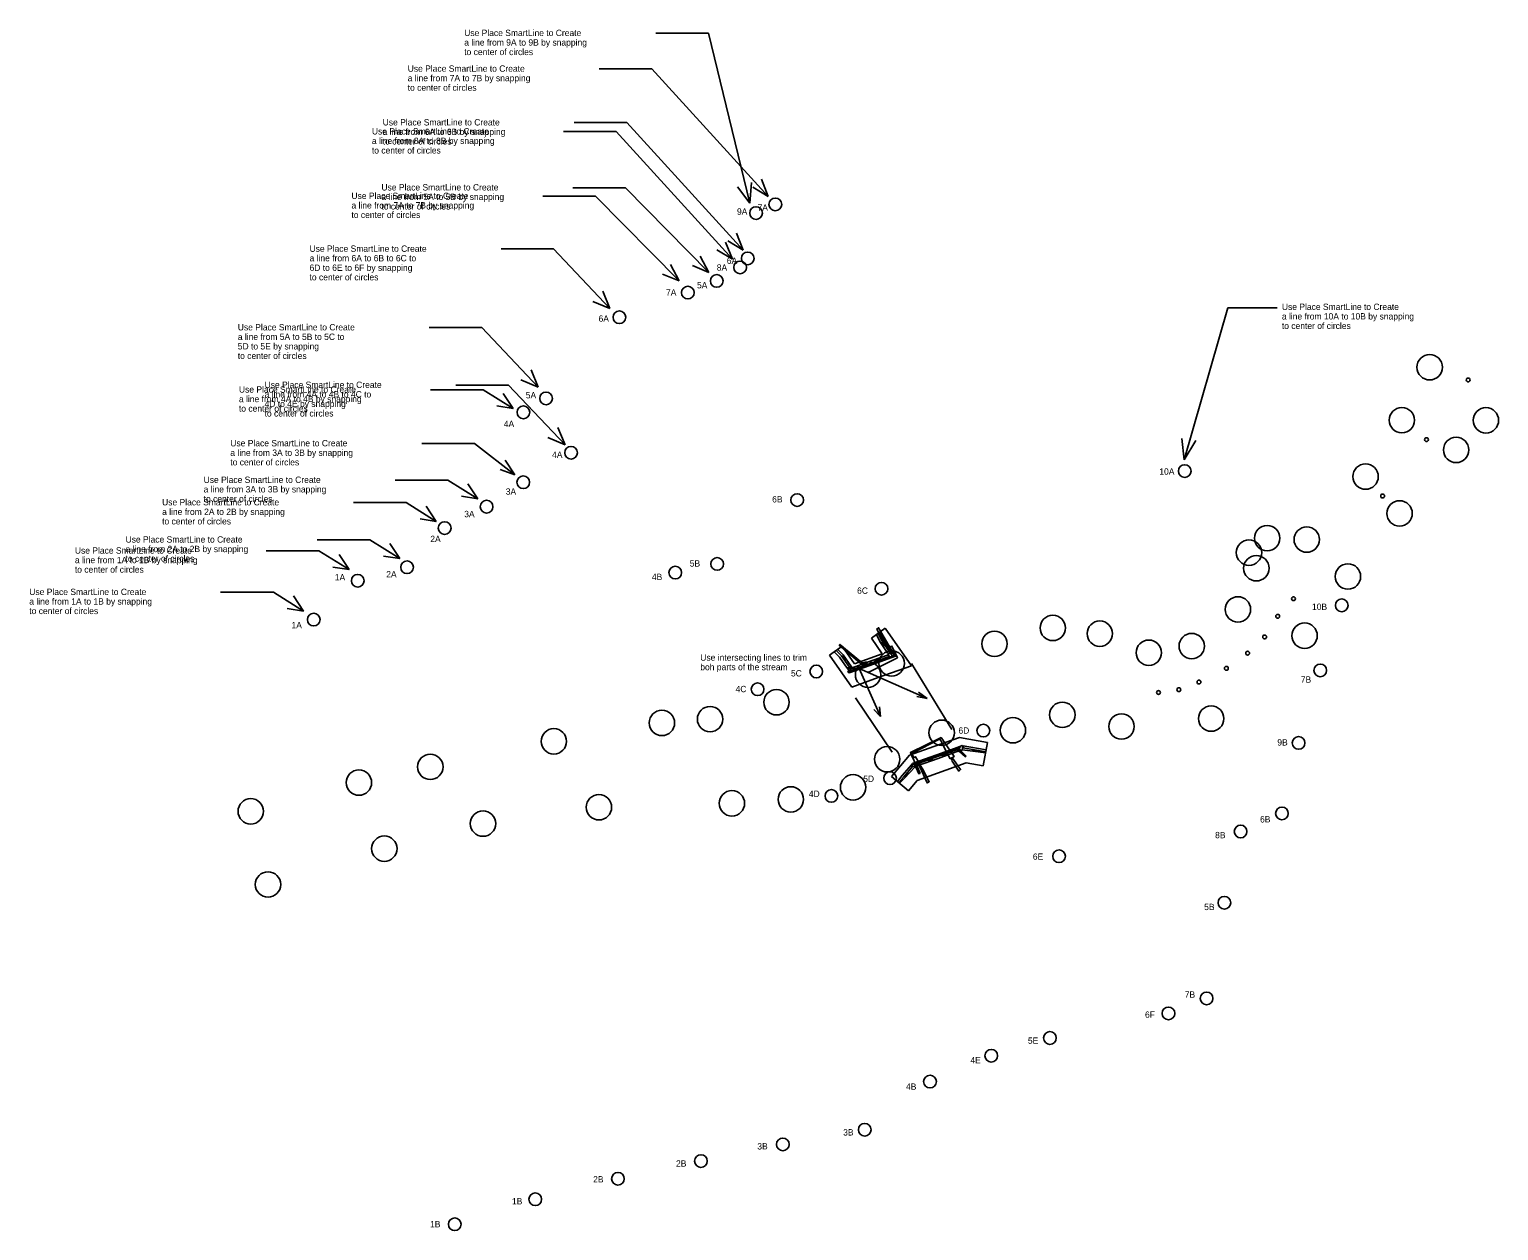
# Model space of a CAD drawing. Extents: x 74477 to 81269, y 49330 to 50934.
# Drawn here: x 74477 to 75634, y 49330 to 50276 of the extents above; entities that cross this region are included whole.
import ezdxf

# ---------------------------------------------------------------- set-up
doc = ezdxf.new("R2010")
doc.units = 0
for name, color, linetype in [('1', 7, 'Continuous'), ('13', 7, 'Continuous'), ('2', 7, 'Continuous'), ('3', 7, 'Continuous'), ('4', 7, 'Continuous'), ('5', 7, 'Continuous'), ('6', 7, 'Continuous')]:
    doc.layers.add(name, color=color, linetype=linetype)

msp = doc.modelspace()

# ---------------------------------------------------------------- linework, layer by layer
at = {"layer": '1'}
for points in [[(75156.2, 49784.7), (75157.2, 49785.3), (75155.7, 49787.9), (75155.5, 49787.9), (75145.7, 49804.9), (75144.2, 49803.9), (75149.4, 49794.7), (75153.4, 49787.8), (75154.9, 49786.9)], [(75134.7, 49773.5), (75133.2, 49775), (75131, 49777.3), (75114.7, 49791.2), (75115.2, 49791.8), (75131.5, 49778.5), (75134, 49776.2), (75135.4, 49774.1)], [(75154.6, 49789.8), (75156.2, 49790.5), (75160.6, 49781.3), (75137.4, 49769.7), (75137, 49770.4)], [(75194, 49717.1), (75195.4, 49714.8), (75195.4, 49714.3), (75202.2, 49701.8), (75205.2, 49703.5), (75197, 49715.4), (75196.8, 49715.8), (75194.9, 49718.5), (75170.8, 49706.6), (75172.5, 49702.9), (75172.6, 49702.4), (75174.6, 49698.2), (75177.1, 49699.3), (75174.8, 49703.4), (75173.5, 49702.8), (75173.2, 49703.1), (75171.8, 49705.9), (75193.6, 49717.2)], [(75176.7, 49698.8), (75183.9, 49682.8), (75185.6, 49683.7), (75180.3, 49693.8), (75177.2, 49698.8)], [(75177.2, 49698.8), (75176.7, 49698.8)], [(75203.1, 49701.9), (75203.6, 49700), (75209, 49692), (75210.3, 49693.2), (75204.8, 49701.2), (75203.9, 49702.2)], [(75203.9, 49702.2), (75203.1, 49701.9)]]:
    msp.add_lwpolyline(points, dxfattribs=at)
at = {"layer": '13'}
for centre in [(75579.7, 50010.1), (75557.8, 49968.4), (75624, 49968.3), (75600.5, 49945), (75529.2, 49924), (75556, 49895), (75451.7, 49875.5), (75482.9, 49874.4), (75437.4, 49864.1), (75443.2, 49851.8), (75515.3, 49845.3), (75428.7, 49819.4), (75282.9, 49804.8), (75319.9, 49800.3), (75481.2, 49798.7), (75237, 49792.3), (75392.3, 49790.5), (75156, 49776.9), (75358.5, 49785.3), (75137.4, 49768), (75065.3, 49746.3), (74975.1, 49730), (75013, 49733), (75290.4, 49736.4), (75407.6, 49733.4), (75195.4, 49722.3), (75251.5, 49724.2), (75337, 49727.2), (74890, 49715.5), (74792.7, 49695.4), (75152.5, 49701.4), (74736.5, 49683), (75125.6, 49679.3), (74651.3, 49660.4), (74925.5, 49663.6), (75030.2, 49666.7), (75076.6, 49669.8), (74834.2, 49650.7), (74756.5, 49631), (74664.9, 49602.8)]:
    msp.add_circle(centre, 10, dxfattribs=at)
at = {"layer": '2'}
for p, q in [((75151, 49804.5), (75140, 49796.8)), ((75144.1, 49799.7), (75146.9, 49801.6)), ((75146.6, 49794.2), (75144.1, 49799.7)), ((75145.5, 49800.6), (75148, 49795.2)), ((75146.9, 49801.6), (75149.4, 49796.2)), ((75171.5, 49775), (75151, 49804.5)), ((75107.1, 49783.4), (75117.1, 49790.4)), ((75115, 49781.8), (75110.8, 49786)), ((75116.5, 49782.8), (75112.2, 49787)), ((75113.5, 49787.9), (75117.7, 49783.7)), ((75117.1, 49790.4), (75126.8, 49776.5)), ((75140, 49796.8), (75148.6, 49784.3)), ((75153.1, 49784.7), (75146.6, 49794.2)), ((75149, 49793.7), (75147.6, 49792.7)), ((75148, 49795.2), (75154.8, 49785.3)), ((75149.5, 49792.9), (75148.1, 49791.9)), ((75149.3, 49793.3), (75148.6, 49792.8)), ((75150.1, 49792.1), (75148.7, 49791.1)), ((75149.8, 49792.5), (75149.1, 49792)), ((75150.7, 49791.3), (75149.2, 49790.3)), ((75149.4, 49796.2), (75156.5, 49785.9)), ((75150.4, 49791.7), (75149.7, 49791.2)), ((75156.5, 49785.9), (75153.1, 49784.7)), ((75107.1, 49783.4), (75124.6, 49758.2)), ((75121, 49773.1), (75115, 49781.8)), ((75122.7, 49773.8), (75116.5, 49782.8)), ((75118.2, 49783), (75116.9, 49782.1)), ((75117.2, 49781.7), (75117.8, 49782.2)), ((75118.8, 49782.2), (75117.5, 49781.3)), ((75117.7, 49783.7), (75124.4, 49774.3)), ((75117.7, 49780.9), (75118.4, 49781.3)), ((75119.3, 49781.4), (75118, 49780.5)), ((75118.3, 49780.1), (75118.9, 49780.5)), ((75119.9, 49780.6), (75118.6, 49779.7)), ((75124.4, 49774.3), (75121, 49773.1)), ((75121.8, 49769.9), (75141.4, 49777)), ((75123.4, 49769.7), (75141.6, 49776.2)), ((75140.6, 49779.1), (75124.9, 49773.5)), ((75125.8, 49772.2), (75141.1, 49777.7)), ((75148.6, 49784.3), (75126.8, 49776.5)), ((75133.8, 49775), (75133.3, 49776.5)), ((75134.3, 49775.2), (75134, 49775.9)), ((75134.8, 49775.4), (75134.2, 49776.8)), ((75135.2, 49775.5), (75135, 49776.3)), ((75135.7, 49775.7), (75135.2, 49777.2)), ((75136.2, 49775.9), (75135.9, 49776.6)), ((75136.6, 49776.1), (75136.1, 49777.5)), ((75138.6, 49775.2), (75138.2, 49775)), ((75140.6, 49779.1), (75153.4, 49783.7)), ((75154, 49782.3), (75141.1, 49777.7)), ((75141.4, 49777), (75159.6, 49783.5)), ((75141.6, 49776.2), (75158.9, 49782.5)), ((75143.2, 49778.4), (75142.7, 49779.9)), ((75143.7, 49778.6), (75143.4, 49779.3)), ((75144.1, 49778.7), (75143.6, 49780.2)), ((75144.6, 49778.9), (75144.3, 49779.6)), ((75145.1, 49779.1), (75144.5, 49780.6)), ((75145.5, 49779.2), (75145.3, 49780)), ((75145.4, 49765.7), (75171.5, 49775)), ((75146, 49779.4), (75145.5, 49780.9)), ((75153.4, 49783.7), (75154, 49782.3)), ((75124.6, 49758.2), (75145.4, 49765.7)), ((75124.9, 49773.5), (75125.8, 49772.2)), ((75209.3, 49718.6), (75189.2, 49711.4)), ((75231.4, 49714.6), (75209.3, 49718.6)), ((75170.1, 49704.6), (75156, 49687.9)), ((75189.2, 49711.4), (75170.1, 49704.6)), ((75191.6, 49704.9), (75172.9, 49698.2)), ((75208.5, 49711), (75191.6, 49704.9)), ((75210.1, 49710.8), (75191.8, 49704.2)), ((75208, 49709.2), (75192.1, 49703.5)), ((75192.6, 49702.1), (75208.8, 49708)), ((75194.6, 49706), (75195, 49706.2)), ((75195.8, 49704.8), (75196.3, 49703.5)), ((75196.2, 49705), (75196.5, 49704.3)), ((75196.7, 49705.2), (75197.2, 49703.8)), ((75197.2, 49705.3), (75197.4, 49704.7)), ((75197.7, 49705.5), (75198.2, 49704.1)), ((75198.1, 49705.7), (75198.4, 49705)), ((75198.6, 49705.9), (75199.1, 49704.5)), ((75209.4, 49709.7), (75208, 49709.2)), ((75209.3, 49707.3), (75208, 49709.2)), ((75208, 49709.2), (75209.3, 49707.3)), ((75208.8, 49708), (75208, 49709.2)), ((75209.7, 49707.5), (75208.4, 49709.4)), ((75208.5, 49711), (75211.6, 49712.1)), ((75208.5, 49711), (75209.4, 49709.7)), ((75209.9, 49707.7), (75208.7, 49709.5)), ((75213.9, 49703.2), (75209.3, 49707.3)), ((75210.5, 49708.1), (75209.4, 49709.7)), ((75213.9, 49703.2), (75209.7, 49707.5)), ((75214.1, 49703.4), (75209.9, 49707.7)), ((75211.5, 49708.8), (75210.5, 49708.1)), ((75210.5, 49708.1), (75214.6, 49703.9)), ((75212.1, 49712), (75211.5, 49708.8)), ((75211.6, 49712.1), (75212.1, 49712)), ((75211.6, 49708.8), (75212.2, 49712)), ((75224.1, 49707.2), (75211.6, 49708.8)), ((75212, 49710.5), (75224.3, 49708.3)), ((75212.2, 49712), (75224.5, 49709.8)), ((75212.5, 49710.4), (75212.7, 49711.9)), ((75219.3, 49707.8), (75219.6, 49709.2)), ((75220.1, 49709.1), (75220, 49708.6)), ((75220.3, 49707.7), (75220.6, 49709)), ((75221.1, 49708.9), (75221, 49708.5)), ((75221.3, 49707.6), (75221.6, 49708.8)), ((75222.1, 49708.7), (75222, 49708.4)), ((75222.3, 49707.4), (75222.5, 49708.6)), ((75229.9, 49706.5), (75224.1, 49707.2)), ((75224.3, 49708.3), (75230.1, 49707.3)), ((75224.5, 49709.8), (75230.4, 49708.7)), ((75231.4, 49714.6), (75228.1, 49696.2)), ((75164.4, 49688.5), (75171.5, 49696.9)), ((75165.5, 49687.6), (75172.6, 49696)), ((75173.9, 49694.9), (75166.4, 49686.8)), ((75172.3, 49695.6), (75171.2, 49696.5)), ((75171.5, 49696.9), (75173.9, 49694.9)), ((75172.5, 49698.1), (75171.6, 49697)), ((75171.6, 49697), (75174.1, 49694.9)), ((75191.8, 49704.2), (75172.3, 49697.2)), ((75172.9, 49698.2), (75172.5, 49698.1)), ((75172.9, 49698.2), (75173.8, 49697)), ((75173.8, 49697), (75175.2, 49697.5)), ((75175, 49695.2), (75173.8, 49697)), ((75174.1, 49694.9), (75175, 49695.2)), ((75175.7, 49695.6), (75174.5, 49697.2)), ((75175.9, 49695.8), (75174.8, 49697.3)), ((75175, 49695.2), (75177.5, 49689.9)), ((75175.2, 49697.5), (75176.2, 49696)), ((75175.6, 49697.6), (75192.1, 49703.5)), ((75176.1, 49696.2), (75175.6, 49697.6)), ((75176.2, 49696), (75175.7, 49697.6)), ((75178.2, 49690.2), (75175.7, 49695.6)), ((75178.4, 49690.3), (75175.9, 49695.8)), ((75192.6, 49702.1), (75176.1, 49696.2)), ((75176.2, 49684.7), (75214.8, 49698.6)), ((75178.4, 49690.3), (75176.2, 49696)), ((75185, 49701), (75185.5, 49699.6)), ((75185.5, 49701.1), (75185.7, 49700.4)), ((75185.9, 49701.3), (75186.4, 49699.9)), ((75186.4, 49701.5), (75186.6, 49700.8)), ((75186.9, 49701.6), (75187.4, 49700.3)), ((75187.3, 49701.8), (75187.6, 49701.1)), ((75187.8, 49702), (75188.3, 49700.6)), ((75214.6, 49703.9), (75213.9, 49703.2)), ((75228.1, 49696.2), (75214.8, 49698.6)), ((75156, 49687.9), (75169.3, 49676.6)), ((75160.6, 49684), (75164.4, 49688.5)), ((75162.3, 49682.5), (75160.6, 49684)), ((75161.7, 49683), (75165.5, 49687.6)), ((75166.4, 49686.8), (75162.3, 49682.5)), ((75166.2, 49688.3), (75167.1, 49687.6)), ((75166.5, 49688.7), (75166.8, 49688.5)), ((75166.8, 49689.1), (75167.8, 49688.3)), ((75167.2, 49689.5), (75167.5, 49689.2)), ((75167.5, 49689.8), (75168.4, 49689)), ((75167.8, 49690.2), (75168.1, 49689.9)), ((75168.1, 49690.6), (75169.1, 49689.8)), ((75169.3, 49676.6), (75176.2, 49684.7)), ((75177.5, 49689.9), (75178.4, 49690.3))]:
    msp.add_line(p, q, dxfattribs=at)
for points in [[(75158.9, 49782.5), (75156.6, 49785.8), (75153.2, 49784.5), (75153.4, 49783.7)], [(75123.4, 49769.7), (75121.1, 49773), (75124.4, 49774.2), (75124.9, 49773.5)], [(75154.9, 49785.2), (75156.3, 49783.1), (75158, 49783.7)], [(75158.9, 49782.5), (75159.9, 49782.8), (75159, 49784.1), (75158, 49783.7), (75158.9, 49782.5)], [(75123.4, 49769.7), (75122.4, 49769.4), (75121.5, 49770.6), (75122.5, 49771), (75123.4, 49769.7)], [(75122.5, 49771), (75124.2, 49771.6), (75122.8, 49773.6)]]:
    msp.add_lwpolyline(points, dxfattribs=at)
at = {"layer": '3'}
for p, q in [((75203.4, 49724.9), (75171.6, 49776.8)), ((75130.5, 49772.8), (75121.3, 49772.8)), ((75147.1, 49735), (75130.5, 49772.8)), ((75130.5, 49772.8), (75183.9, 49749.2)), ((75183.9, 49749.2), (75175.7, 49750.8)), ((75183.9, 49749.2), (75177.2, 49754.2)), ((75156.3, 49706.9), (75127.4, 49749.8)), ((75147.1, 49735), (75141.9, 49740.6)), ((75147.1, 49735), (75146.4, 49742.6))]:
    msp.add_line(p, q, dxfattribs=at)
at = {"layer": '4'}
for centre in [(75610, 50000.1), (75577.2, 49953.1), (75542.6, 49908.7), (75472.5, 49827.8), (75460, 49814), (75449.7, 49797.7), (75436.3, 49784.9), (75419.6, 49773), (75398, 49762.2), (75366.1, 49754), (75382.1, 49756.2)]:
    msp.add_circle(centre, 1.5, dxfattribs=at)
at = {"layer": '5'}
for p, q in [((74970.2, 50273.2), (75011.7, 50273.2)), ((75044.3, 50139.3), (75011.7, 50273.2)), ((74897.5, 50195.7), (74939, 50195.7)), ((75030.7, 50095.1), (74939, 50195.7)), ((75044.3, 50139.3), (75045.6, 50155.6)), ((74881.4, 50144.9), (74922.9, 50144.9)), ((74922.9, 50144.9), (74988.6, 50078.1)), ((75044.3, 50139.3), (75034.7, 50152.2)), ((74848.4, 50103.3), (74889.8, 50103.3)), ((74889.8, 50103.3), (74934.2, 50056.3)), ((75030.7, 50095.1), (75018.4, 50102.6)), ((75030.7, 50095.1), (75025.2, 50108.7)), ((74988.6, 50078.1), (74981.8, 50091)), ((74988.6, 50078.1), (74975.6, 50083.5)), ((74934.2, 50056.3), (74928.5, 50069.9)), ((74934.2, 50056.3), (74920.6, 50062)), ((75386.4, 49937.2), (75420.8, 50056.8)), ((75420.8, 50056.8), (75459.6, 50056.8)), ((74791.8, 50041.4), (74833.3, 50041.4)), ((74833.3, 50041.4), (74877.7, 49994.5)), ((74877.7, 49994.5), (74872, 50008.1)), ((74877.7, 49994.5), (74864.1, 50000.2)), ((74792.8, 49992.4), (74834.3, 49992.4)), ((74834.3, 49992.4), (74858, 49977.6)), ((74858, 49977.6), (74850.1, 49989.5)), ((74858, 49977.6), (74845.2, 49979.6)), ((75386.4, 49937.2), (75384.5, 49953.9)), ((75386.4, 49937.2), (75395.5, 49952.5)), ((74764.9, 49921.3), (74806.4, 49921.3)), ((74806.4, 49921.3), (74830.1, 49906.5)), ((74830.1, 49906.5), (74822.2, 49918.4)), ((74830.1, 49906.5), (74817.3, 49908.5)), ((74703.5, 49874.3), (74745, 49874.3)), ((74745, 49874.3), (74768.7, 49859.4)), ((74768.7, 49859.4), (74760.8, 49871.3)), ((74768.7, 49859.4), (74755.8, 49861.4)), ((74627.6, 49832.9), (74669.1, 49832.9)), ((74669.1, 49832.9), (74692.8, 49818.1)), ((74692.8, 49818.1), (74680, 49820.1)), ((74692.8, 49818.1), (74684.9, 49830))]:
    msp.add_line(p, q, dxfattribs=at)
for centre in [(75049.2, 50131.5), (75036.7, 50088.7), (74995.5, 50068.9), (74941.6, 50049.5), (74883.9, 49985.6), (74866, 49974.6), (75386.8, 49928.3), (74837, 49900.3), (75081.6, 49905.5), (74774.4, 49852.6), (75018.6, 49855.2), (75148, 49835.7), (75510.4, 49822.6), (74700.9, 49811.4), (75096.6, 49770.5), (75228.2, 49724), (75476.5, 49714.3), (75154.8, 49686.5), (75430.8, 49644.5), (75287.8, 49625), (75404, 49513.1), (75374, 49501.3), (75280.6, 49481.9), (75186.2, 49447.6), (75070.3, 49398.1), (74940.4, 49371), (74812, 49335.2)]:
    msp.add_circle(centre, 5, dxfattribs=at)
at = {"layer": '6'}
for p, q in [((74925.6, 50245.1), (74967.1, 50245.1)), ((75058.8, 50144.5), (74967.1, 50245.1)), ((74905.9, 50202.8), (74947.4, 50202.8)), ((75039.1, 50102.2), (74947.4, 50202.8)), ((75058.8, 50144.5), (75053.4, 50158.1)), ((74904.9, 50151.5), (74946.4, 50151.5)), ((74946.4, 50151.5), (75012.1, 50084.8)), ((75058.8, 50144.5), (75046.6, 50152)), ((75039.1, 50102.2), (75026.9, 50109.7)), ((75039.1, 50102.2), (75033.7, 50115.8)), ((75012.1, 50084.8), (74999.2, 50090.2)), ((75012.1, 50084.8), (75005.3, 50097.7)), ((74812.9, 49996.1), (74854.4, 49996.1)), ((74854.4, 49996.1), (74898.8, 49949.1)), ((74898.8, 49949.1), (74893.1, 49962.7)), ((74785.9, 49950.1), (74827.4, 49950.1)), ((74827.4, 49950.1), (74859.3, 49925.3)), ((74898.8, 49949.1), (74885.2, 49954.8)), ((74859.3, 49925.3), (74851.6, 49936.9)), ((74859.3, 49925.3), (74847.7, 49929.7)), ((74732.2, 49903.6), (74773.7, 49903.6)), ((74773.7, 49903.6), (74797.4, 49888.7)), ((74797.4, 49888.7), (74784.6, 49890.7)), ((74797.4, 49888.7), (74789.5, 49900.6)), ((74663.5, 49865.6), (74705, 49865.6)), ((74705, 49865.6), (74728.7, 49850.7)), ((74728.7, 49850.7), (74720.8, 49862.6)), ((74728.7, 49850.7), (74715.9, 49852.7))]:
    msp.add_line(p, q, dxfattribs=at)
for centre in [(75064.4, 50138.3), (75042.7, 50095.8), (75018.3, 50078.1), (74903.6, 49942.8), (74865.9, 49919.5), (74804, 49883.4), (74735.6, 49842), (74985.6, 49848.4), (75493.5, 49771.4), (75050.4, 49756.5), (75108.6, 49672.5), (75463.3, 49658.7), (75418, 49588.4), (75234.4, 49467.9), (75134.8, 49409.6), (75005.8, 49385), (74875.3, 49354.9)]:
    msp.add_circle(centre, 5, dxfattribs=at)

# ---------------------------------------------------------------- texts
at = {"layer": '3'}
for s, p in [('boh parts of the stream', (75005.3, 49771.5)), ('Use intersecting lines to trim', (75005.3, 49779))]:
    msp.add_text(s, height=5, dxfattribs=at).set_placement(p)
at = {"layer": '5'}
for s, p in [('Use Place SmartLine to Create', (74819.4, 50270.9)), ('to center of circles', (74819.4, 50255.9)), ('a line from 9A to 9B by snapping', (74819.4, 50263.4)), ('a line from 8A to 8B by snapping', (74746.7, 50185.9)), ('Use Place SmartLine to Create', (74746.7, 50193.4)), ('to center of circles', (74746.7, 50178.4)), ('Use Place SmartLine to Create', (74730.6, 50142.6)), ('to center of circles', (74730.6, 50127.6)), ('a line from 7A to 7B by snapping', (74730.6, 50135.1)), ('9A', (75034.2, 50130.2)), ('a line from 6A to 6B to 6C to', (74697.6, 50093.5)), ('Use Place SmartLine to Create', (74697.6, 50101)), ('6D to 6E to 6F by snapping', (74697.6, 50086)), ('8A', (75018.3, 50086.1)), ('to center of circles', (74697.6, 50078.5)), ('7A', (74978.3, 50066.5)), ('a line from 10A to 10B by snapping', (75463.3, 50047.7)), ('Use Place SmartLine to Create', (75463.3, 50055.2)), ('Use Place SmartLine to Create', (74641.1, 50039.1)), ('6A', (74925.2, 50045.9)), ('to center of circles', (75463.3, 50040.2)), ('a line from 5A to 5B to 5C to', (74641.1, 50031.6)), ('5D to 5E by snapping', (74641.1, 50024.1)), ('to center of circles', (74641.1, 50016.6)), ('Use Place SmartLine to Create', (74642, 49990.1)), ('a line from 4A to 4B by snapping', (74642, 49982.6)), ('5A', (74867.9, 49985.6)), ('to center of circles', (74642, 49975.1)), ('4A', (74850.6, 49963)), ('Use Place SmartLine to Create', (74614.2, 49919)), ('10A', (75366.8, 49925.5)), ('a line from 3A to 3B by snapping', (74614.2, 49911.5)), ('to center of circles', (74614.2, 49904)), ('6B', (75061.9, 49903.6)), ('3A', (74819.4, 49892)), ('a line from 2A to 2B by snapping', (74552.7, 49864.5)), ('Use Place SmartLine to Create', (74552.7, 49872)), ('to center of circles', (74552.7, 49857)), ('5B', (74997, 49853.1)), ('2A', (74758, 49844.6)), ('Use Place SmartLine to Create', (74476.9, 49830.7)), ('6C', (75128.8, 49831.7)), ('to center of circles', (74476.9, 49815.7)), ('a line from 1A to 1B by snapping', (74476.9, 49823.2)), ('10B', (75487, 49819)), ('1A', (74683.4, 49804.5)), ('5C', (75076.7, 49766.6)), ('6D', (75208.6, 49721.5)), ('9B', (75459.7, 49712.2)), ('5D', (75133.6, 49683.5)), ('8B', (75410.7, 49639.2)), ('6E', (75267.2, 49622.2)), ('7B', (75386.8, 49513.6)), ('6F', (75355.5, 49497.8)), ('5E', (75263.3, 49477.3)), ('4B', (75167.3, 49441.1)), ('3B', (75050.2, 49394.1)), ('2B', (74920.9, 49368.1)), ('1B', (74792.5, 49332.8))]:
    msp.add_text(s, height=5, dxfattribs=at).set_placement(p)
at = {"layer": '6'}
for s, p in [('a line from 7A to 7B by snapping', (74774.9, 50235.3)), ('Use Place SmartLine to Create', (74774.9, 50242.8)), ('to center of circles', (74774.9, 50227.8)), ('Use Place SmartLine to Create', (74755.2, 50200.5)), ('to center of circles', (74755.2, 50185.5)), ('a line from 6A to 6B by snapping', (74755.2, 50193)), ('a line from 5A to 5B by snapping', (74754.2, 50141.8)), ('Use Place SmartLine to Create', (74754.2, 50149.3)), ('to center of circles', (74754.2, 50134.3)), ('7A', (75050.4, 50133.3)), ('6A', (75026.2, 50091.5)), ('5A', (75002.7, 50072.2)), ('Use Place SmartLine to Create', (74662.2, 49993.8)), ('4D to 4E by snapping', (74662.2, 49978.8)), ('a line from 4A to 4B to 4C to', (74662.2, 49986.3)), ('to center of circles', (74662.2, 49971.3)), ('Use Place SmartLine to Create', (74635.2, 49947.8)), ('to center of circles', (74635.2, 49932.8)), ('a line from 3A to 3B by snapping', (74635.2, 49940.3)), ('4A', (74888.6, 49938.7)), ('3A', (74852.1, 49909.7)), ('Use Place SmartLine to Create', (74581.5, 49901.3)), ('to center of circles', (74581.5, 49886.3)), ('a line from 2A to 2B by snapping', (74581.5, 49893.8)), ('Use Place SmartLine to Create', (74512.8, 49863.3)), ('2A', (74792.7, 49872.4)), ('a line from 1A to 1B by snapping', (74512.8, 49855.8)), ('to center of circles', (74512.8, 49848.3)), ('1A', (74717.5, 49842.2)), ('4B', (74967.2, 49842.5)), ('7B', (75478.2, 49761.7)), ('4C', (75033.1, 49754.2)), ('4D', (75090.8, 49671.7)), ('6B', (75446.1, 49651.6)), ('5B', (75402.1, 49582.6)), ('4E', (75218, 49461.9)), ('3B', (75117.8, 49405.1)), ('2B', (74986.2, 49380.6)), ('1B', (74857, 49350.8))]:
    msp.add_text(s, height=5, dxfattribs=at).set_placement(p)

doc.saveas('drawing.dxf')
